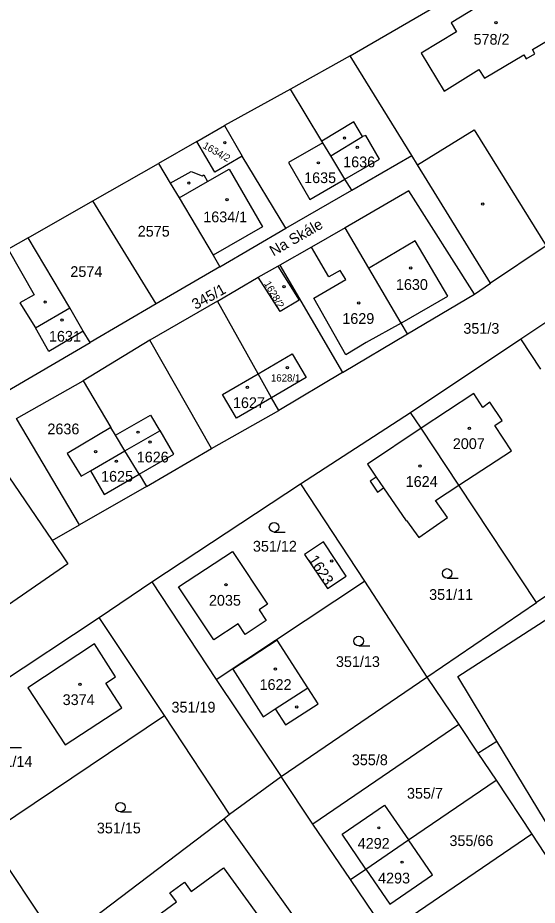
# Model space of a CAD drawing. Extents: x -679220 to -673243, y -1075091 to -1066557.
# Drawn here: x -675965.1 to -675883, y -1072696.2 to -1072555.7 of the extents above; entities that cross this region are included whole.
import ezdxf

# ---------------------------------------------------------------- set-up
doc = ezdxf.new("R2010")
doc.units = 0
for name, color, linetype in [('Hranice parcel', 7, 'Continuous'), ('Parcelní čísla', 7, 'Continuous'), ('Pop  PČ popisy', 7, 'Continuous'), ('Vnitřní kresba', 7, 'Continuous'), ('Značky budov', 7, 'Continuous'), ('Značky kultur', 7, 'Continuous')]:
    doc.layers.add(name, color=color, linetype=linetype)

msp = doc.modelspace()

# ---------------------------------------------------------------- linework, layer by layer
at = {"layer": 'Hranice parcel'}
for p, q in [((-675912.55, -1072561.77), (-675885.46, -1072546.01)), ((-675912.55, -1072561.77), (-675922.01, -1072567.03)), ((-675902.79, -1072577.57), (-675912.55, -1072561.77)), ((-675922.01, -1072567.03), (-675932.43, -1072572.8)), ((-675936.79, -1072575.33), (-675932.43, -1072572.8)), ((-675932.43, -1072572.8), (-675929.64, -1072577.67)), ((-675936.79, -1072575.33), (-675942.85, -1072578.79)), ((-675922.74, -1072589.04), (-675929.64, -1072577.67)), ((-675912.3, -1072583.04), (-675902.79, -1072577.57)), ((-675953.27, -1072584.73), (-675942.85, -1072578.79)), ((-675922.74, -1072589.04), (-675912.3, -1072583.04)), ((-675963.48, -1072590.55), (-675953.27, -1072584.73)), ((-675943.26, -1072601.01), (-675953.27, -1072584.73)), ((-675933.17, -1072595.16), (-675922.74, -1072589.04)), ((-675933.17, -1072595.16), (-675943.26, -1072601.01)), ((-675927.08, -1072596.78), (-675923.98, -1072595.05)), ((-675923.98, -1072595.05), (-675923.67, -1072594.9)), ((-675923.67, -1072594.9), (-675913.76, -1072611.86)), ((-675933.55, -1072600.6), (-675927.08, -1072596.78)), ((-675892.89, -1072599.49), (-675890.34, -1072597.72)), ((-675903.47, -1072605.78), (-675892.89, -1072599.49)), ((-675933.55, -1072600.6), (-675944.25, -1072606.79)), ((-675943.26, -1072601.01), (-675953.67, -1072607.15)), ((-675885.57, -1072606.55), (-675878.69, -1072601.99)), ((-675913.76, -1072611.86), (-675903.47, -1072605.78)), ((-675944.25, -1072606.79), (-675954.8, -1072613.18)), ((-675934.51, -1072623.93), (-675944.25, -1072606.79)), ((-675903.02, -1072618.22), (-675885.57, -1072606.55)), ((-675882.39, -1072611.33), (-675885.57, -1072606.55)), ((-675913.76, -1072611.86), (-675923.85, -1072617.88)), ((-675954.8, -1072613.18), (-675950.4, -1072620.56)), ((-675934.51, -1072623.93), (-675923.85, -1072617.88)), ((-675920.42, -1072629.48), (-675903.02, -1072618.22)), ((-675901.34, -1072620.71), (-675903.02, -1072618.22)), ((-675895.35, -1072629.73), (-675901.34, -1072620.71)), ((-675944.77, -1072629.9), (-675934.51, -1072623.93)), ((-675966.54, -1072628.38), (-675959.67, -1072638.48)), ((-675945.91, -1072627.99), (-675944.77, -1072629.9)), ((-675944.77, -1072629.9), (-675955.35, -1072635.99)), ((-675943.9, -1072645.03), (-675920.42, -1072629.48)), ((-675920.42, -1072629.48), (-675910.28, -1072644.91)), ((-675883.05, -1072648.27), (-675895.35, -1072629.73)), ((-675959.67, -1072638.48), (-675955.35, -1072635.99)), ((-675865.73, -1072636.59), (-675883.05, -1072648.27)), ((-675952.24, -1072650.63), (-675943.9, -1072645.03)), ((-675943.9, -1072645.03), (-675933.75, -1072660.45)), ((-675933.75, -1072660.45), (-675910.28, -1072644.91)), ((-675910.28, -1072644.91), (-675900.4, -1072660.07)), ((-675900.4, -1072660.07), (-675883.05, -1072648.27)), ((-675980.59, -1072669.35), (-675952.24, -1072650.63)), ((-675941.94, -1072666.18), (-675952.24, -1072650.63)), ((-675933.75, -1072660.45), (-675923.48, -1072675.82)), ((-675923.48, -1072675.82), (-675900.4, -1072660.07)), ((-675900.4, -1072660.07), (-675895.36, -1072667.58)), ((-675970.1, -1072685.1), (-675941.94, -1072666.18)), ((-675931.61, -1072681.79), (-675941.94, -1072666.18)), ((-675895.36, -1072667.58), (-675918.44, -1072683.37)), ((-675895.36, -1072667.58), (-675892.33, -1072672.12)), ((-675892.33, -1072672.12), (-675889.34, -1072670.21)), ((-675878.83, -1072687.64), (-675889.34, -1072670.21)), ((-675892.33, -1072672.12), (-675889.46, -1072676.41)), ((-675931.61, -1072681.79), (-675923.48, -1072675.82)), ((-675918.44, -1072683.37), (-675923.48, -1072675.82)), ((-675903.3, -1072685.85), (-675889.46, -1072676.41)), ((-675889.46, -1072676.41), (-675883.79, -1072684.91)), ((-675932.52, -1072682.5), (-675931.61, -1072681.79)), ((-675956.96, -1072701), (-675932.52, -1072682.5)), ((-675912.49, -1072692.13), (-675918.44, -1072683.37)), ((-675970.1, -1072685.1), (-675958.65, -1072702.36)), ((-675883.79, -1072684.91), (-675906.75, -1072700.57)), ((-675883.79, -1072684.91), (-675866.89, -1072711.12)), ((-675910.05, -1072690.47), (-675903.3, -1072685.85)), ((-675912.49, -1072692.13), (-675910.05, -1072690.47)), ((-675906.75, -1072700.57), (-675912.49, -1072692.13))]:
    msp.add_line(p, q, dxfattribs=at)
for points in [[(-675912.3, -1072583.04), (-675913.39, -1072581.3), (-675915.62, -1072577.6), (-675916.88, -1072575.52), (-675917.03, -1072575.27), (-675922.01, -1072567.03)], [(-675929.64, -1072577.67), (-675933.98, -1072580.18), (-675936.79, -1072575.33)], [(-675890.34, -1072597.72), (-675901.9, -1072579), (-675902.79, -1072577.57)], [(-675942.85, -1072578.79), (-675941, -1072581.91), (-675939.61, -1072584.25), (-675934.23, -1072593.31), (-675933.17, -1072595.16)], [(-675864.4, -1072580.56), (-675881.54, -1072591.86), (-675890.34, -1072597.72)], [(-675892.89, -1072599.49), (-675903.25, -1072583.12), (-675913.32, -1072588.98)], [(-675913.32, -1072588.98), (-675918.66, -1072592.03), (-675923.67, -1072594.9)], [(-675903.47, -1072605.78), (-675904.48, -1072604.05), (-675909.58, -1072595.36), (-675913.32, -1072588.98)], [(-675963.48, -1072590.55), (-675966.66, -1072592.36), (-675981.32, -1072600.73)], [(-675953.67, -1072607.15), (-675954.76, -1072605.36), (-675956.92, -1072601.65), (-675963.48, -1072590.55)], [(-675923.98, -1072595.05), (-675920.61, -1072600.43), (-675923.64, -1072602.25), (-675927.08, -1072596.78)], [(-675981.32, -1072600.73), (-675971.14, -1072617.3), (-675953.67, -1072607.15)], [(-675923.85, -1072617.88), (-675924.98, -1072615.87), (-675927.1, -1072612.09), (-675933.55, -1072600.6)], [(-675955.35, -1072635.99), (-675965.32, -1072619.16), (-675954.8, -1072613.18)], [(-675895.35, -1072629.73), (-675887.04, -1072624.27), (-675889.67, -1072620.27), (-675888.5, -1072619.5), (-675890.44, -1072616.56), (-675891.55, -1072617.41), (-675893, -1072615.2), (-675901.34, -1072620.71)], [(-675950.4, -1072620.56), (-675957.32, -1072624.69), (-675955.11, -1072628.3), (-675953.64, -1072627.45), (-675951.45, -1072631.19), (-675945.91, -1072627.99)], [(-675945.91, -1072627.99), (-675948.17, -1072624.29), (-675949.66, -1072621.8), (-675950.4, -1072620.56)], [(-675901.34, -1072620.71), (-675909.82, -1072626.41), (-675908.45, -1072628.42), (-675909.39, -1072629.07), (-675908.21, -1072630.79), (-675907.27, -1072630.15), (-675903.71, -1072635.36), (-675903.61, -1072635.29), (-675901.71, -1072638.01), (-675897.15, -1072634.83), (-675899.05, -1072632.11), (-675895.35, -1072629.73)], [(-675959.67, -1072638.48), (-675957.19, -1072642.13), (-675981.86, -1072659.13)], [(-675913.18, -1072644.1), (-675916.78, -1072638.69), (-675919.75, -1072640.68), (-675916.14, -1072646.08), (-675913.18, -1072644.1)], [(-675934.11, -1072654.19), (-675939.68, -1072645.77), (-675931.17, -1072640.18), (-675925.61, -1072648.56), (-675926.94, -1072649.44), (-675925.83, -1072651.12), (-675929.16, -1072653.34), (-675930.28, -1072651.65), (-675934.11, -1072654.19)], [(-675889.34, -1072670.21), (-675895.49, -1072660.01), (-675865.07, -1072640.36), (-675858.4, -1072650.51)], [(-675919.23, -1072661.76), (-675924.07, -1072654.23), (-675931.12, -1072658.82), (-675926.31, -1072666.34), (-675924.41, -1072665.11), (-675922.79, -1072667.64), (-675917.6, -1072664.3), (-675919.23, -1072661.76)], [(-675951.21, -1072661.04), (-675949.65, -1072660.02), (-675952.98, -1072654.84), (-675963.55, -1072661.76), (-675957.65, -1072670.8), (-675948.68, -1072664.94), (-675951.21, -1072661.04)], [(-675910.05, -1072690.47), (-675913.83, -1072684.95), (-675907.09, -1072680.32), (-675903.3, -1072685.85)], [(-675932.52, -1072682.5), (-675914.95, -1072707.09), (-675914.07, -1072710.21), (-675915.43, -1072712.32), (-675936.33, -1072728.12)], [(-675910.05, -1072690.47), (-675906.28, -1072696), (-675899.5, -1072691.39), (-675903.3, -1072685.85)], [(-675946.26, -1072707.98), (-675949.95, -1072702.92), (-675940, -1072695.66), (-675941.06, -1072694.21), (-675938.78, -1072692.54), (-675937.72, -1072693.99), (-675932.59, -1072690.25), (-675922.15, -1072704.67), (-675922.5, -1072706.94), (-675924.28, -1072708.27), (-675926.56, -1072707.92), (-675931.58, -1072711.57), (-675933.18, -1072711.35), (-675935.31, -1072708.5), (-675935.08, -1072707.1), (-675934.98, -1072707.01), (-675938.45, -1072702.23), (-675946.26, -1072707.98)]]:
    msp.add_lwpolyline(points, dxfattribs=at)
at = {"layer": 'Vnitřní kresba'}
for p, q in [((-675883.81, -1072548.72), (-675896.57, -1072556.57)), ((-675896.57, -1072556.57), (-675895.73, -1072557.99)), ((-675895.73, -1072557.99), (-675901.32, -1072561.33)), ((-675883.71, -1072560.79), (-675878.39, -1072557.61)), ((-675901.32, -1072561.33), (-675897.69, -1072567.38)), ((-675884.7, -1072562.26), (-675883.33, -1072561.44)), ((-675883.33, -1072561.44), (-675883.71, -1072560.79)), ((-675891.27, -1072565.31), (-675885.09, -1072561.61)), ((-675885.09, -1072561.61), (-675884.7, -1072562.26)), ((-675897.69, -1072567.38), (-675892.19, -1072563.94)), ((-675892.19, -1072563.94), (-675891.27, -1072565.31)), ((-675911.98, -1072572.22), (-675917.03, -1072575.27)), ((-675910.57, -1072574.55), (-675911.98, -1072572.22)), ((-675901.9, -1072579), (-675892.95, -1072573.48)), ((-675892.95, -1072573.48), (-675881.54, -1072591.86)), ((-675916.88, -1072575.52), (-675922.3, -1072578.67)), ((-675915.62, -1072577.6), (-675910.57, -1072574.55)), ((-675910.05, -1072574.38), (-675910.57, -1072574.55)), ((-675907.91, -1072578.12), (-675910.05, -1072574.38)), ((-675913.39, -1072581.3), (-675907.91, -1072578.12)), ((-675935.1, -1072581.68), (-675931.68, -1072579.72)), ((-675931.68, -1072579.72), (-675926.39, -1072588.82)), ((-675922.3, -1072578.67), (-675918.92, -1072584.5)), ((-675941, -1072581.91), (-675937.7, -1072580.1)), ((-675937.7, -1072580.1), (-675935.97, -1072580.77)), ((-675935.97, -1072580.77), (-675935.72, -1072580.61)), ((-675935.72, -1072580.61), (-675935.1, -1072581.68)), ((-675939.61, -1072584.25), (-675935.1, -1072581.68)), ((-675918.92, -1072584.5), (-675913.39, -1072581.3)), ((-675926.39, -1072588.82), (-675934.23, -1072593.31)), ((-675902.24, -1072591.05), (-675909.4, -1072595.26)), ((-675897.1, -1072599.81), (-675902.24, -1072591.05)), ((-675966.66, -1072592.36), (-675962.55, -1072599.57)), ((-675915.9, -1072596.72), (-675918.66, -1072592.03)), ((-675909.4, -1072595.26), (-675909.58, -1072595.36)), ((-675914.14, -1072595.72), (-675915.9, -1072596.72)), ((-675913.25, -1072597.17), (-675914.14, -1072595.72)), ((-675918.31, -1072600.14), (-675913.25, -1072597.17)), ((-675962.55, -1072599.57), (-675964.8, -1072600.86)), ((-675964.8, -1072600.86), (-675962.34, -1072604.8)), ((-675913.23, -1072609.06), (-675918.31, -1072600.14)), ((-675904.3, -1072603.95), (-675897.1, -1072599.81)), ((-675962.34, -1072604.8), (-675956.92, -1072601.65)), ((-675960.24, -1072608.55), (-675962.34, -1072604.8)), ((-675904.48, -1072604.05), (-675910, -1072607.12)), ((-675904.3, -1072603.95), (-675904.48, -1072604.05)), ((-675954.76, -1072605.36), (-675960.24, -1072608.55)), ((-675910, -1072607.12), (-675913.23, -1072609.06)), ((-675927.1, -1072612.09), (-675921.71, -1072608.95)), ((-675921.71, -1072608.95), (-675919.53, -1072612.69)), ((-675932.73, -1072615.36), (-675927.1, -1072612.09)), ((-675919.53, -1072612.69), (-675924.98, -1072615.87)), ((-675930.55, -1072619.13), (-675932.73, -1072615.36)), ((-675924.98, -1072615.87), (-675930.55, -1072619.13)), ((-675949.66, -1072621.8), (-675944.13, -1072618.61)), ((-675944.13, -1072618.61), (-675942.68, -1072621.12)), ((-675948.17, -1072624.29), (-675942.68, -1072621.12)), ((-675942.68, -1072621.12), (-675942.59, -1072621.07)), ((-675940.43, -1072624.81), (-675942.59, -1072621.07)), ((-675953.64, -1072627.45), (-675948.17, -1072624.29)), ((-675945.91, -1072627.99), (-675940.43, -1072624.81)), ((-675908.45, -1072628.42), (-675907.27, -1072630.15)), ((-675924.41, -1072665.11), (-675919.23, -1072661.76))]:
    msp.add_line(p, q, dxfattribs=at)
at = {"layer": 'Značky budov'}
for centre in [(-675889.48, -1072556.52), (-675932.38, -1072575.52), (-675913.45, -1072574.78), (-675911.43, -1072576.26), (-675917.58, -1072578.7), (-675938.07, -1072581.91), (-675932.03, -1072584.53), (-675891.58, -1072585.22), (-675902.96, -1072595.33), (-675923, -1072598.31), (-675960.8, -1072600.73), (-675911.19, -1072600.88), (-675958.12, -1072603.59), (-675922.48, -1072611.11), (-675928.81, -1072614.24), (-675893.69, -1072620.73), (-675946.11, -1072621.32), (-675944.2, -1072622.89), (-675952.81, -1072624.4), (-675949.53, -1072625.92), (-675901.5, -1072626.68), (-675915.47, -1072641.7), (-675932.19, -1072645.47), (-675924.38, -1072658.8), (-675955.29, -1072661.23), (-675921, -1072664.8), (-675908.02, -1072683.93), (-675904.33, -1072689.36)]:
    msp.add_circle(centre, 0.175, dxfattribs=at)
at = {"layer": 'Značky kultur'}
for p, q in [((-675924.59, -1072637.12), (-675922.84, -1072637.12)), ((-675897.21, -1072644.42), (-675895.46, -1072644.42)), ((-675911.2, -1072655.12), (-675909.45, -1072655.12)), ((-675966.31, -1072671.24), (-675964.56, -1072671.24)), ((-675948.89, -1072681.41), (-675947.14, -1072681.41))]:
    msp.add_line(p, q, dxfattribs=at)
for centre in [(-675924.59, -1072636.37), (-675897.21, -1072643.67), (-675911.2, -1072654.37), (-675948.89, -1072680.66)]:
    msp.add_circle(centre, 0.75, dxfattribs=at)

# ---------------------------------------------------------------- texts
at = {"layer": 'Parcelní čísla'}
for s, height, p in [('578/2', 1.7, (-675893.03, -1072560.01)), ('1636', 1.7, (-675913.65, -1072579.41)), ('1635', 1.7, (-675919.83, -1072581.91)), ('1634/1', 1.7, (-675935.79, -1072588.11)), ('2575', 1.7, (-675946.15, -1072590.38)), ('2574', 1.7, (-675956.81, -1072596.76)), ('1630', 1.7, (-675905.31, -1072598.81)), ('1629', 1.7, (-675913.79, -1072604.19)), ('351/3', 1.7, (-675894.64, -1072605.75)), ('1631', 1.7, (-675960.2, -1072607)), ('1628/1', 1.14, (-675925.08, -1072613.31)), ('1627', 1.7, (-675931.09, -1072617.51)), ('2636', 1.7, (-675960.44, -1072621.66)), ('2007', 1.7, (-675896.31, -1072623.99)), ('1626', 1.7, (-675946.31, -1072626.11)), ('1625', 1.7, (-675951.95, -1072629.16)), ('1624', 1.7, (-675903.76, -1072629.98)), ('351/12', 1.7, (-675927.93, -1072640.22)), ('2035', 1.7, (-675934.89, -1072648.78)), ('351/11', 1.7, (-675900.05, -1072647.86)), ('351/13', 1.7, (-675914.8, -1072658.48)), ('1622', 1.7, (-675926.88, -1072662.11)), ('3374', 1.7, (-675958.03, -1072664.5)), ('351/19', 1.7, (-675940.81, -1072665.69)), ('351/14', 1.7, (-675969.77, -1072674.28)), ('355/8', 1.7, (-675912.28, -1072674.02)), ('355/7', 1.7, (-675903.56, -1072679.31)), ('351/15', 1.7, (-675952.62, -1072684.81)), ('355/66', 1.7, (-675896.84, -1072686.81)), ('4292', 1.7, (-675911.35, -1072687.24)), ('4293', 1.7, (-675908.13, -1072692.73))]:
    msp.add_text(s, height=height, dxfattribs=at).set_placement(p)
for s, height, rotation, p in [('1634/2', 1.14, 330, (-675935.97, -1072576.29)), ('345/1', 1.7, 29, (-675937.01, -1072601.99)), ('1628/2', 1.14, 300, (-675926.22, -1072597.81)), ('1623', 1.7, 303, (-675919.23, -1072641.46))]:
    msp.add_text(s, height=height, rotation=rotation, dxfattribs=at).set_placement(p)
at = {"layer": 'Pop  PČ popisy'}
msp.add_text('Na Skále', height=1.7, rotation=30, dxfattribs=at).set_placement((-675924.68, -1072593.54))

doc.saveas('drawing.dxf')
